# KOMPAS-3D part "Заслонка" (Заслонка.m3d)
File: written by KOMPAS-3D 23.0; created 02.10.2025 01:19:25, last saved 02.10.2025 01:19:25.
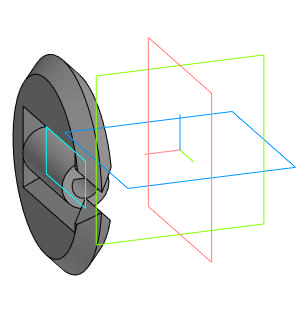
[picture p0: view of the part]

Document properties: Автор: Inspektor_Kot; Полное имя файла: I:\Autodesk Inventor Projects\ИМ-ИТ ЦД\Вариант 8\Заслонка.m3d

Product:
- Part/product: Заслонка

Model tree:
1. Эскиз:1  (with: Элемент выдавливания:4)
2. Элемент выдавливания:1
     Расстояние 1 = -28
3. Эскиз:2  (with: Элемент выдавливания:1)
4. Элемент выдавливания:2
     Расстояние 1 = 3
5. Нормальная плоскость:1  (with: Элемент выдавливания:1)
     Угол = 90
6. Эскиз:3  (with: Элемент выдавливания:1, Элемент выдавливания:4, Элемент выдавливания:2)
7. Элемент выдавливания:3
     Расстояние 1 = 10; Угол 1 = 45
